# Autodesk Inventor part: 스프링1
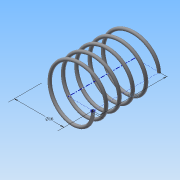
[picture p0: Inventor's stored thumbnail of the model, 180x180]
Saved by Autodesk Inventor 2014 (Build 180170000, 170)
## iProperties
Created: 2015-06
Part Number: 스프링1
Material: 강철, 연강
Document SubType Name: Modeling
Designer: MYHOME
Density: 7.86 g/cm^3
Appearance: 강철
Mass: 1.53479 g
Surface Area: 7.89194 cm^2
Volume: 0.195266 cm^3
Author: MYHOME
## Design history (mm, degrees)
sketch "스케치1"
  geometry: L1 (0, 0)-(8, 0); L2 (8, 0)-(8, 21.5); L3 (8, 21.5)-(0, 21.5); L4 (0, 21.5)-(0, 0); C1 r 0.5 at (8, 0)
  constraints: 8 end point, 2 parallel, 1 centre point, 1 coincident, 1 horizontal, 1 perpendicular
  dimensions: "d0" = 16 diameter of L2 L4; "d1" = 21.5 distance of L1.end L2.end (derived); "d2" = 1 diameter of C1
feature "코일2" sketch "스케치1" pitch "d17" = 10; turns "d19" = 5; dims "d18" = 21.5 (= d1), "d20" = 0, angle "d21" = 90 deg, angle "d22" = 90 deg, "d23" = 0, "d24" = 0
node "작업 평면3"
sketch "스케치4"
  geometry: L1 (-8.5, 0)-(-7.5, 0) reference; 1 further point
  constraints: 1 horizontal alignment
extrude "돌출3" cut sketch "스케치4" stored distance "d26" = 10; taper "d27" = 0 deg
node "작업 평면4"
sketch "스케치5"
  geometry: L1 (-7.5, 0)-(-8.5, 0) reference; 1 further point
  constraints: 1 horizontal alignment
extrude "돌출4" cut sketch "스케치5" stored distance "d29" = 10; taper "d30" = 0 deg
node "솔리드2"
node "절단 모서리 투영3"
node "절단 모서리 투영4"
other parameters: "d25" = 0, "d28" = 21.5 (= d1)
